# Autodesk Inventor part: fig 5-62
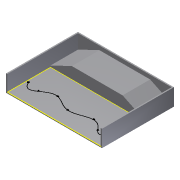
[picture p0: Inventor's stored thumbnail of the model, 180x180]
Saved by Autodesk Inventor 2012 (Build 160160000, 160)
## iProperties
Created: 2004-05
Part Number: fig 5-62
Document SubType Name: Modeling
Designer: CADCIM Technologies
Manufacturer: Standard
Standards Organization: Custom
Density: 1 g/cm^3
Material: Default
Author: CADCIM Technologies
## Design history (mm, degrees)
sketch "Sketch1"
  geometry: L1 (-40, -30)-(40, -30); L2 (40, -30)-(40, 30); L3 (40, 30)-(-40, 30); L4 (-40, 30)-(-40, -30); 1 further point
  constraints: 8 end point, 2 parallel, 1 horizontal, 1 perpendicular, 1 other
  dimensions: "d0" = 80 distance of L1.start L1.end; "d1" = 60 distance of L3.end L1.start; "d2" = 30 distance from line of point (0, 0) L1; "d3" = 40 distance from line of point (0, 0) L4
extrude "Extrusion1" new body sketch "Sketch1" distance "d4" = 14; taper "d5" = 0 deg
shell "Shell1" dims "d6" = 1
workplane "Work Plane1"
sketch "Sketch2"
  geometry: L1 (78, -13)-(78, -11.813); L2 (0, -11.813)-(0, -13); L3 (0, -13)-(78, -13); L4 (0, -11.813)-(17.826, -3.295); L5 (17.826, -3.295)-(60.174, -3.295); L6 (60.174, -3.295)-(78, -11.813); L7 (79, -13.795)-(78, -13.795); L8 (78, 0)-(78, -13) reference; L9 (0, -13)-(0, 0) reference; L10 (78, -13)-(0, -13) reference
  constraints: 14 end point, 3 collinear, 2 equal length, 2 vertical, 1 horizontal alignment, 1 parallel, 1 point on line
extrude "Extrusion2" join sketch "Sketch2" stored distance "d8" = 14; taper "d9" = 0 deg
workplane "Work Plane2"
sketch "Sketch4"
  geometry: L1 (78, 36)-(0, 36) reference; L2 (0, 36)-(0, 0) reference; L3 (78, 0)-(0, 0) reference; L4 (78, 0)-(78, 36) reference; 7 further points
  constraints: 7 other
body "Solid1"
other parameters: "d7" = 23, "d18" = 4
